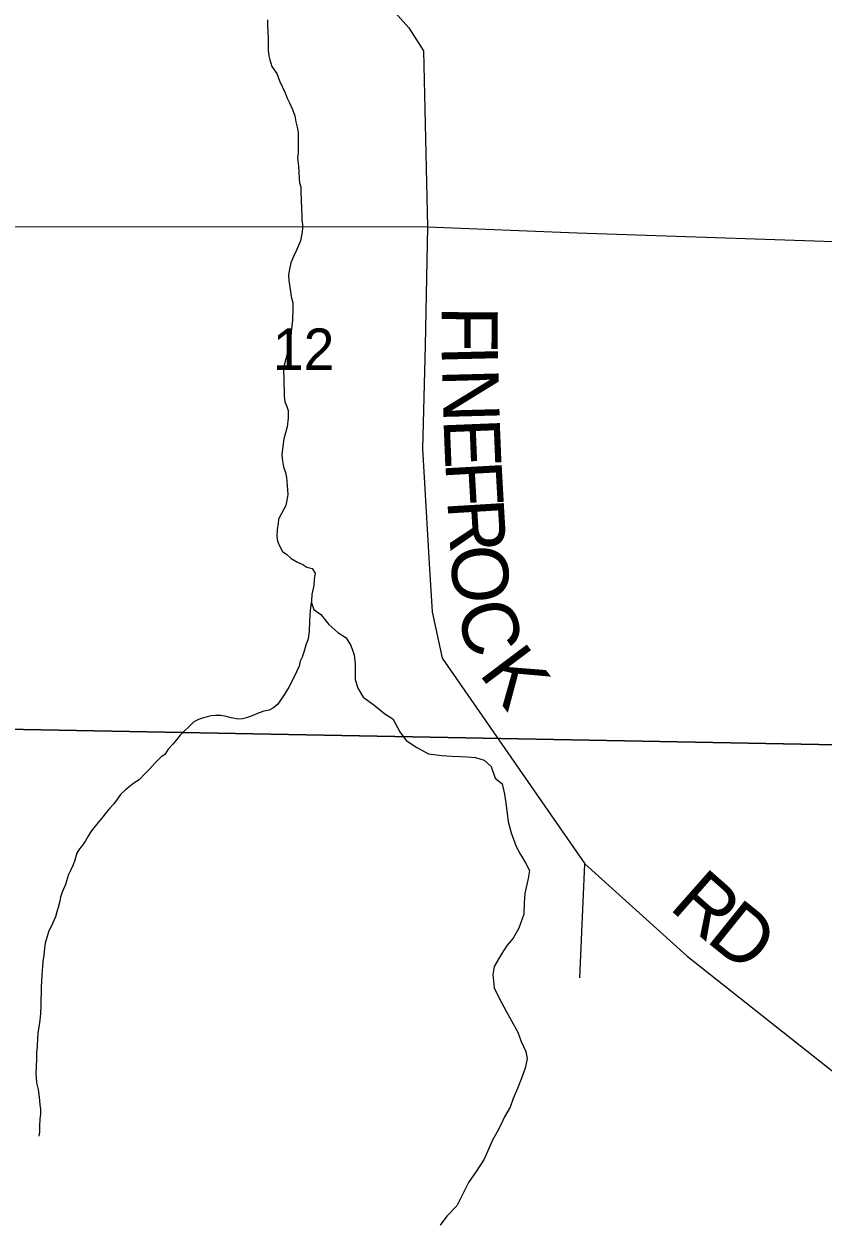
# Model space of a CAD drawing. Extents: x 36.7 to 70.7, y 0 to 22.
# Drawn here: x 40.424 to 41.231, y 17.404 to 18.615 of the extents above; entities that cross this region are included whole.
import ezdxf

# ---------------------------------------------------------------- set-up
doc = ezdxf.new("R2010")
doc.units = 0
for name, color, linetype in [('GM_X_County_Road', 7, 'Continuous'), ('GM_X_County_Road_Text', 7, 'Continuous'), ('GM_X_Minor_River', 7, 'Continuous'), ('GM_X_Section', 7, 'Continuous'), ('GM_X_Section_Text', 7, 'Continuous'), ('GM_X_Township_Road', 7, 'Continuous')]:
    doc.layers.add(name, color=color, linetype=linetype)

msp = doc.modelspace()

# ---------------------------------------------------------------- linework, layer by layer
at = {"layer": 'GM_X_County_Road'}
for points in [[(40.6386, 19.034), (40.6524, 18.9963), (40.6705, 18.9177), (40.6909, 18.7655), (40.6995, 18.7384), (40.8129, 18.6112), (40.8277, 18.5878), (40.8318, 18.4101)], [(40.8318, 18.4101), (40.8294, 18.29), (40.8266, 18.1856), (40.8334, 18.07), (40.8364, 18.021), (40.8467, 17.9741), (40.9906, 17.7663), (41.0943, 17.6731), (41.2664, 17.5366)]]:
    msp.add_lwpolyline(points, dxfattribs=at)
at = {"layer": 'GM_X_Minor_River'}
for points in [[(40.6703, 18.6193), (40.6703, 18.614), (40.6706, 18.6064), (40.6709, 18.6011), (40.6708, 18.5924), (40.6707, 18.5882), (40.6714, 18.5829), (40.6725, 18.5787), (40.6747, 18.5722), (40.6796, 18.565), (40.6822, 18.5577), (40.6881, 18.5455), (40.6899, 18.5402), (40.6925, 18.5352), (40.6955, 18.5287), (40.6977, 18.5223), (40.6988, 18.5162), (40.7002, 18.5108), (40.7013, 18.5055), (40.701, 18.4846), (40.7006, 18.4797), (40.7016, 18.471), (40.702, 18.4657), (40.7023, 18.4588), (40.7026, 18.4546), (40.7037, 18.4505), (40.704, 18.4444), (40.7043, 18.4379), (40.7046, 18.4277), (40.7049, 18.4216), (40.7048, 18.4167), (40.7055, 18.4125), (40.7055, 18.4079), (40.705, 18.403), (40.7034, 18.3958), (40.6995, 18.3864), (40.6968, 18.3807), (40.6937, 18.3735), (40.6925, 18.3671), (40.6913, 18.3614), (40.6916, 18.3557), (40.6934, 18.3447), (40.6941, 18.3397), (40.6959, 18.3333), (40.6958, 18.3276), (40.6953, 18.3158), (40.6941, 18.3044), (40.6936, 18.2987), (40.6912, 18.2889), (40.69, 18.2821), (40.6888, 18.2768), (40.6868, 18.2688), (40.6864, 18.2647), (40.6867, 18.2563), (40.6866, 18.2521), (40.6869, 18.2438), (40.6869, 18.2388), (40.6876, 18.2331), (40.6898, 18.2286), (40.6909, 18.2244), (40.6912, 18.2168), (40.6899, 18.2081), (40.6867, 18.1959), (40.6859, 18.191), (40.6855, 18.185), (40.6847, 18.18), (40.685, 18.1755), (40.6864, 18.1675), (40.6883, 18.1618), (40.6893, 18.1568), (40.69, 18.1488), (40.6907, 18.1397), (40.6902, 18.1356), (40.6886, 18.1284), (40.684, 18.1197), (40.6813, 18.1148), (40.6808, 18.1106), (40.68, 18.1038), (40.6795, 18.097), (40.6803, 18.0924), (40.6825, 18.0871), (40.6854, 18.0821), (40.6896, 18.079), (40.6941, 18.0748), (40.7005, 18.0713), (40.7058, 18.069), (40.7099, 18.0663), (40.7152, 18.0647), (40.7182, 18.0601), (40.7174, 18.054), (40.7169, 18.0476), (40.7149, 18.0385), (40.7145, 18.0321), (40.7132, 18.0226), (40.7128, 18.0173), (40.7127, 18.0116)], [(40.7143, 18.031), (40.717, 18.0233), (40.7242, 18.0183), (40.732, 18.0083), (40.7414, 18.0003), (40.7497, 17.9949), (40.7542, 17.9869), (40.7578, 17.9777), (40.7589, 17.9682), (40.7587, 17.9526), (40.7616, 17.9439), (40.7668, 17.9347), (40.7777, 17.927), (40.7886, 17.9178), (40.7969, 17.9128), (40.804, 17.8998), (40.8103, 17.891), (40.8209, 17.884), (40.8329, 17.8775), (40.8462, 17.8758), (40.8564, 17.8753), (40.8648, 17.8748), (40.872, 17.8744), (40.8803, 17.8739), (40.889, 17.8712), (40.8961, 17.8646), (40.9002, 17.8528), (40.9073, 17.8471), (40.9095, 17.8368), (40.9109, 17.8277), (40.9133, 17.809), (40.9162, 17.7976), (40.9214, 17.7839), (40.9259, 17.7759), (40.9307, 17.7675), (40.9348, 17.7598), (40.9335, 17.7515), (40.93, 17.7364), (40.9295, 17.7269), (40.929, 17.7155), (40.9242, 17.7015), (40.9184, 17.6913), (40.9123, 17.6842), (40.9061, 17.6748), (40.8991, 17.6627), (40.8979, 17.6547), (40.8993, 17.641), (40.9037, 17.6319), (40.9115, 17.617), (40.9167, 17.6078), (40.923, 17.5964), (40.9264, 17.5869), (40.9312, 17.5766), (40.9326, 17.5693), (40.9306, 17.5599), (40.9263, 17.5489), (40.9228, 17.5395), (40.9185, 17.5293), (40.9154, 17.5206), (40.9096, 17.5108), (40.9064, 17.5032), (40.9022, 17.4956), (40.8975, 17.4873), (40.889, 17.4681), (40.8809, 17.4556), (40.8731, 17.4443), (40.8658, 17.4296), (40.8615, 17.4209), (40.8515, 17.4104), (40.8446, 17.4014)], [(40.7127, 18.0116), (40.7122, 18.0013), (40.7114, 17.9938), (40.709, 17.9873), (40.707, 17.9801), (40.7051, 17.9752), (40.7031, 17.9711), (40.7023, 17.9662), (40.6996, 17.9605), (40.6969, 17.9548), (40.6918, 17.945), (40.6864, 17.936), (40.6834, 17.9318), (40.6806, 17.9277), (40.6761, 17.9239), (40.6719, 17.9217), (40.6665, 17.9206), (40.6616, 17.9191), (40.6555, 17.9162), (40.649, 17.914), (40.6448, 17.9129), (40.6406, 17.9125), (40.6335, 17.9138), (40.6285, 17.9153), (40.6229, 17.9161), (40.6175, 17.9162), (40.6134, 17.9159), (40.6092, 17.9148), (40.6046, 17.9137), (40.6004, 17.9122), (40.5959, 17.91), (40.5912, 17.9051), (40.5859, 17.9006), (40.582, 17.8965), (40.5782, 17.8916), (40.5744, 17.8874), (40.5697, 17.8822), (40.5666, 17.8769), (40.5624, 17.8743), (40.5567, 17.8683), (40.5513, 17.8623), (40.5471, 17.8581), (40.5406, 17.8514), (40.5352, 17.848), (40.5268, 17.8413), (40.5218, 17.8364), (40.5187, 17.8319), (40.5149, 17.827), (40.511, 17.8228), (40.5076, 17.8187), (40.5026, 17.8123), (40.4991, 17.8082), (40.4949, 17.8029), (40.4914, 17.7984), (40.4891, 17.7942), (40.4864, 17.7897), (40.4837, 17.7856), (40.4802, 17.7814), (40.4775, 17.7773), (40.4755, 17.7701), (40.474, 17.7655), (40.4716, 17.7603), (40.4693, 17.7557), (40.4661, 17.7455), (40.4626, 17.7376), (40.4611, 17.7327), (40.4603, 17.7285), (40.4587, 17.7224), (40.4575, 17.7179), (40.4559, 17.713), (40.452, 17.7039), (40.4493, 17.6986), (40.4473, 17.6918), (40.4457, 17.6861), (40.4449, 17.6812), (40.4441, 17.674), (40.4433, 17.6676), (40.4428, 17.6626), (40.4423, 17.6547), (40.4419, 17.6475), (40.4414, 17.6422), (40.4412, 17.6228), (40.4408, 17.6152), (40.4403, 17.6084), (40.4391, 17.6012), (40.4383, 17.5955), (40.4378, 17.5894), (40.4374, 17.5826), (40.4369, 17.5754), (40.4368, 17.5686), (40.4364, 17.5621), (40.4363, 17.5549), (40.4369, 17.545), (40.4384, 17.5382), (40.4391, 17.5333), (40.4398, 17.5272), (40.4401, 17.523), (40.4408, 17.5184), (40.4407, 17.5135), (40.4403, 17.5086), (40.4398, 17.5014)], [(40.4398, 17.5014), (40.4398, 17.4957), (40.4393, 17.4911)]]:
    msp.add_lwpolyline(points, dxfattribs=at)
at = {"layer": 'GM_X_Section'}
for points in [[(41.3255, 18.8876), (41.2819, 17.9105), (41.2806, 17.8858), (40.1915, 17.9066), (40.2272, 18.9664)], [(41.2806, 17.8858), (41.2523, 16.9188), (41.2509, 16.8855), (40.1819, 16.9057), (40.1915, 17.9066)]]:
    msp.add_lwpolyline(points, close=True, dxfattribs=at)
at = {"layer": 'GM_X_Township_Road'}
msp.add_line((40.9858, 17.6513), (40.9906, 17.7663), dxfattribs=at)
for points in [[(40.2175, 18.4104), (40.2206, 18.4104), (40.8318, 18.4101)], [(40.8318, 18.4101), (40.9829, 18.4041), (41.3027, 18.3931), (41.3119, 18.3928)]]:
    msp.add_lwpolyline(points, dxfattribs=at)

# ---------------------------------------------------------------- texts
at = {"layer": 'GM_X_County_Road_Text'}
for s, rotation, p in [('F', 269.7814, (40.8461, 18.3301)), ('I', 271.4097, (40.846, 18.29)), ('N', 271.524, (40.8466, 18.2666)), ('E', 272.3129, (40.8479, 18.2157)), ('F', 273.2027, (40.8497, 18.1723)), ('R', 273.4766, (40.8518, 18.1337)), ('O', 273.9435, (40.8547, 18.0867)), ('C', 285.5303, (40.8603, 18.0244)), ('K', 306.946, (40.883, 17.9588)), ('R', 318.5831, (41.0748, 17.7216)), ('D', 321.2116, (41.1119, 17.6889))]:
    msp.add_text(s, height=0.0568, rotation=rotation, dxfattribs=at).set_placement(p)
at = {"layer": 'GM_X_Section_Text'}
msp.add_text('12', height=0.04186, rotation=0, dxfattribs=at).set_placement((40.6755, 18.2655))

doc.saveas('drawing.dxf')
